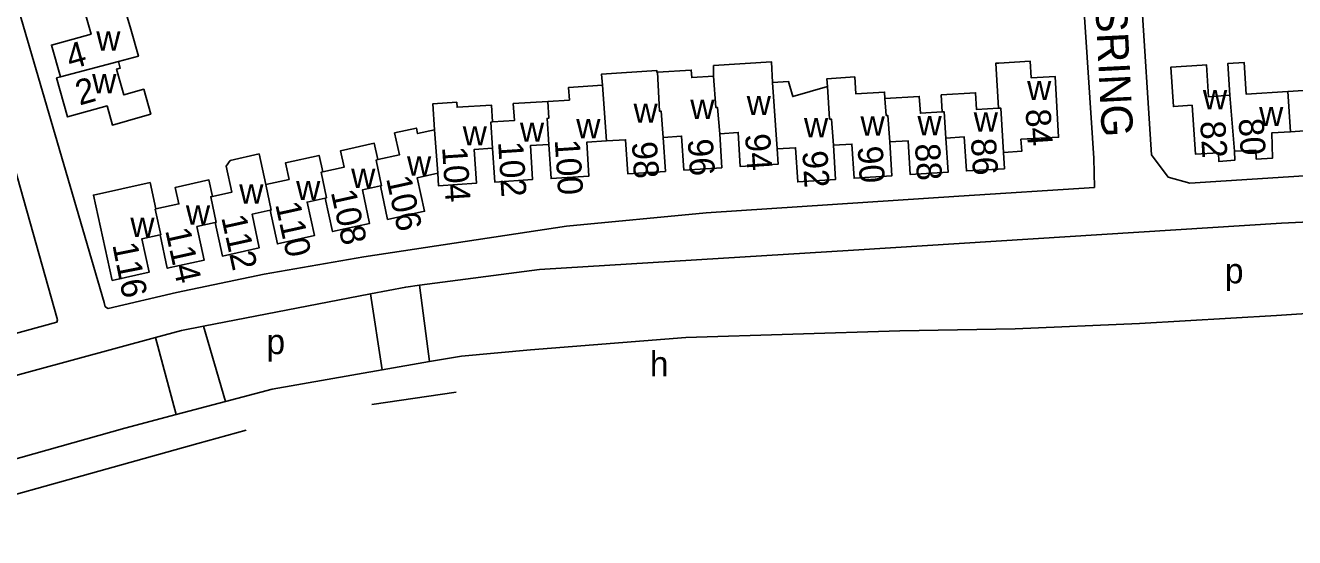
# Model space of a CAD drawing. Extents: x 159441 to 162086, y 388175 to 389787.
# Drawn here: x 160090.5 to 160293, y 388282.9 to 388364.6 of the extents above; entities that cross this region are included whole.
import ezdxf

# ---------------------------------------------------------------- set-up
doc = ezdxf.new("R2010")
doc.units = 0
for name, color, linetype in [('BLT_Basislijn', 7, 'Continuous'), ('BLT_Bebouwing', 7, 'Continuous'), ('BLT_Centroide', 7, 'Continuous'), ('BLT_Huisnummer', 7, 'Continuous'), ('BLT_Huisnummer_ tussenligend', 7, 'Continuous'), ('BLT_Onderverdeling_panden', 7, 'Continuous'), ('BLT_Straatnaam', 7, 'Continuous')]:
    doc.layers.add(name, color=color, linetype=linetype)

msp = doc.modelspace()

# ---------------------------------------------------------------- linework, layer by layer
at = {"layer": 'BLT_Basislijn'}
for p, q in [((160256.8, 388406.25), (160260.99, 388343.47)), ((160103.05, 388320.42), (160085.56, 388380.39)), ((160260.99, 388343.47), (160261.09, 388338.77)), ((160261.09, 388338.77), (160239.41, 388337.36)), ((160239.41, 388337.36), (160199.12, 388334.74)), ((160199.12, 388334.74), (160176.82, 388332.59)), ((160176.82, 388332.59), (160144.51, 388327.71)), ((160144.51, 388327.71), (160128.61, 388324.95)), ((160153.39, 388323.18), (160172.55, 388325.68)), ((160128.61, 388324.95), (160114.6, 388322.05)), ((160114.6, 388322.05), (160103.74, 388319.45)), ((160118.91, 388316.67), (160145.56, 388321.8)), ((160145.56, 388321.8), (160147.41, 388309.68)), ((160153.39, 388323.18), (160155, 388311)), ((160103.26, 388319.74), (160103.05, 388320.42)), ((160103.74, 388319.45), (160103.26, 388319.74)), ((160118.91, 388316.67), (160122.45, 388304.66)), ((160111.29, 388314.87), (160114.54, 388302.55)), ((160160.07, 388311.88), (160155, 388311)), ((160155, 388311), (160147.41, 388309.68)), ((160145.79, 388304.16), (160159.25, 388306.13)), ((160122.45, 388304.66), (160114.54, 388302.55))]:
    msp.add_line(p, q, dxfattribs=at)
for points in [[(160036.37, 388301.08), (160095.52, 388317.29), (160095.65, 388317.66), (160071.61, 388402.93)], [(160268.53, 388369.64), (160270.18, 388343.99), (160272.84, 388340.43), (160276.28, 388339.44), (160347.54, 388344.02)], [(160172.55, 388325.68), (160222.62, 388328.8), (160290.93, 388333.07), (160353.01, 388336.03), (160393.02, 388339)], [(160145.56, 388321.8), (160151.2, 388322.89), (160153.39, 388323.18)], [(160323.1, 388320.51), (160290.1, 388318.37), (160268.27, 388317.06), (160248.4, 388316.24), (160230.01, 388315.91)], [(160111.29, 388314.87), (160115.41, 388315.99), (160118.91, 388316.67)], [(160230.01, 388315.91), (160195.86, 388314.84), (160171.07, 388312.87), (160160.07, 388311.88)], [(160038.47, 388294.65), (160071.9, 388304.16), (160111.29, 388314.87)], [(160147.41, 388309.68), (160129.86, 388306.62), (160122.45, 388304.66)], [(160114.54, 388302.55), (160106.38, 388300.38), (160067.3, 388289.38), (160054.99, 388285.76), (160050.23, 388284.61), (160046.62, 388284.28)], [(160064.32, 388282.94), (160118.04, 388297.92), (160125.75, 388300.05)]]:
    msp.add_lwpolyline(points, dxfattribs=at)
at = {"layer": 'BLT_Bebouwing'}
for points in [[(160100.16, 388366.22), (160100.98, 388363.2), (160094.65, 388361.47), (160096.1, 388356.43)], [(160105.34, 388358.85), (160108.55, 388359.72), (160107.32, 388364), (160106.45, 388367.07), (160106.22, 388367.88)], [(160096.1, 388356.43), (160095.49, 388356.26), (160097.24, 388350.01), (160103.54, 388351.78), (160104.4, 388348.72), (160109.21, 388350.07), (160110.52, 388350.44), (160109.4, 388354.43), (160106.21, 388353.53), (160105.06, 388357.64), (160105.64, 388357.8), (160105.34, 388358.85)], [(160200.32, 388356.53), (160200.3, 388358.2), (160209.56, 388358.8), (160209.71, 388355.51)], [(160245.79, 388351.41), (160245.32, 388358.57), (160245.81, 388358.61), (160250.8, 388358.93), (160250.98, 388356.23), (160254.78, 388356.48), (160255.35, 388346.78), (160249.35, 388346.46), (160249.47, 388344.55), (160246.54, 388344.37)], [(160282.69, 388353.47), (160279.28, 388353.24), (160278.95, 388358.33), (160278.27, 388358.29), (160273.28, 388357.96), (160273.67, 388351.68), (160276.66, 388351.87), (160277.21, 388344.07), (160280.84, 388344.3), (160280.93, 388342.91), (160283.47, 388343.12), (160283.4, 388344.54)], [(160291.92, 388354.06), (160285.29, 388353.63), (160284.96, 388358.72), (160282.37, 388358.55), (160282.69, 388353.47)], [(160301.15, 388354.66), (160300.82, 388359.74), (160298.23, 388359.58), (160298.55, 388354.49), (160291.92, 388354.06)], [(160191.37, 388357.14), (160191.26, 388357.13), (160191.24, 388357.43), (160182.45, 388356.86), (160182.56, 388355.07)], [(160191.37, 388357.14), (160196.74, 388357.49), (160196.82, 388356.3), (160200.32, 388356.53)], [(160218.48, 388354.89), (160218.4, 388356.1), (160222.84, 388356.39), (160223.01, 388353.68), (160227.58, 388353.97), (160227.64, 388352.94)], [(160182.56, 388355.07), (160177.18, 388354.72), (160177.31, 388352.72), (160173.84, 388352.5)], [(160218.48, 388354.89), (160212.93, 388353.27), (160212.28, 388355.67), (160209.71, 388355.51)], [(160236.8, 388350.83), (160236.62, 388353.52), (160242.11, 388353.87), (160242.28, 388351.18), (160245.79, 388351.41)], [(160165.03, 388349.23), (160164.86, 388351.92), (160159.37, 388351.57), (160159.32, 388352.37), (160155.54, 388352.12), (160155.8, 388347.97)], [(160173.84, 388352.5), (160168.35, 388352.14), (160168.52, 388349.45), (160165.03, 388349.23)], [(160227.64, 388352.94), (160233.12, 388353.29), (160233.3, 388350.61), (160236.8, 388350.83)], [(160155.8, 388347.97), (160153.09, 388347.37), (160152.9, 388348.24), (160149.4, 388347.46), (160150.17, 388343.96), (160146.76, 388343.21)], [(160292.33, 388347.67), (160289.35, 388347.48), (160289.49, 388343.47), (160286.9, 388343.3), (160286.83, 388344.71), (160283.4, 388344.54)], [(160301.57, 388345.61), (160298.19, 388345.42), (160298.27, 388344.02), (160295.67, 388343.85), (160295.31, 388347.85), (160292.33, 388347.67)], [(160146.76, 388343.21), (160146.17, 388345.83), (160140.8, 388344.64), (160141.39, 388342.01), (160137.96, 388341.25)], [(160165.04, 388345.02), (160165.38, 388339.63), (160171.41, 388340.02), (160171.08, 388345.45), (160174.04, 388345.63)], [(160174.04, 388345.63), (160174.37, 388340.2), (160180.42, 388340.58), (160180.09, 388346.02), (160183.23, 388346.2)], [(160183.23, 388346.2), (160186.27, 388346.39), (160186.6, 388340.96), (160192.62, 388341.34), (160192.25, 388346.76)], [(160192.25, 388346.76), (160195.2, 388346.96), (160195.57, 388341.54), (160201.62, 388341.91), (160201.28, 388347.35)], [(160201.28, 388347.35), (160204.23, 388347.54), (160204.57, 388342.1), (160210.6, 388342.48), (160210.44, 388344.93)], [(160219.44, 388345.51), (160222.39, 388345.7), (160222.72, 388340.24), (160228.75, 388340.63), (160228.41, 388346.05)], [(160228.41, 388346.05), (160231.34, 388346.23), (160231.68, 388340.82), (160237.71, 388341.21), (160237.36, 388346.65)], [(160246.54, 388344.37), (160246.71, 388341.75), (160240.65, 388341.41), (160240.3, 388346.84), (160237.36, 388346.65)], [(160128.89, 388339.23), (160127.8, 388344.12), (160123.18, 388343.09), (160122.54, 388342.16), (160123.46, 388338.03), (160120.36, 388337.34)], [(160137.96, 388341.25), (160137.37, 388343.89), (160132, 388342.69), (160132.59, 388340.06), (160128.89, 388339.23)], [(160156.29, 388341.03), (160156.41, 388339.05), (160162.46, 388339.45), (160162.12, 388344.84), (160165.04, 388345.02)], [(160210.44, 388344.93), (160213.39, 388345.11), (160213.74, 388339.67), (160219.77, 388340.06), (160219.44, 388345.51)], [(160111.99, 388331.21), (160109.1, 388330.59), (160110.25, 388325.26), (160104.37, 388323.96), (160101.36, 388337.55), (160110.41, 388339.55), (160111.34, 388335.34)], [(160120.36, 388337.34), (160119.78, 388339.98), (160114.41, 388338.78), (160114.99, 388336.15), (160111.34, 388335.34)], [(160147.15, 388339.01), (160148.3, 388333.67), (160154.21, 388334.98), (160153.03, 388340.31), (160156.29, 388341.03)], [(160138.34, 388337.07), (160139.51, 388331.73), (160145.42, 388333.05), (160144.27, 388338.38), (160147.15, 388339.01)], [(160129.57, 388335.13), (160130.73, 388329.78), (160136.63, 388331.1), (160135.46, 388336.43), (160138.34, 388337.07)], [(160120.76, 388333.17), (160121.93, 388327.84), (160127.83, 388329.16), (160126.67, 388334.51), (160129.57, 388335.13)], [(160111.99, 388331.21), (160113.14, 388325.88), (160119.05, 388327.2), (160117.88, 388332.53), (160120.76, 388333.17)]]:
    msp.add_lwpolyline(points, dxfattribs=at)
at = {"layer": 'BLT_Onderverdeling_panden'}
for p, q in [((160096.1, 388356.43), (160105.34, 388358.85)), ((160183.23, 388346.2), (160182.56, 388355.07)), ((160210.44, 388344.93), (160209.71, 388355.51)), ((160291.92, 388354.06), (160292.33, 388347.67)), ((160282.69, 388353.47), (160283.4, 388344.54)), ((160155.8, 388347.97), (160156.29, 388341.03))]:
    msp.add_line(p, q, dxfattribs=at)
for points in [[(160192.25, 388346.76), (160191.94, 388350.96), (160191.66, 388350.94), (160191.37, 388357.14)], [(160201.28, 388347.35), (160200.93, 388351.54), (160200.65, 388351.53), (160200.32, 388356.53)], [(160219.44, 388345.51), (160219.1, 388349.69), (160218.82, 388349.68), (160218.48, 388354.89)], [(160174.04, 388345.63), (160173.73, 388349.78), (160174.01, 388349.8), (160173.84, 388352.5)], [(160228.41, 388346.05), (160228.1, 388350.27), (160227.82, 388350.25), (160227.64, 388352.94)], [(160237.36, 388346.65), (160237.08, 388350.85), (160236.8, 388350.83)], [(160246.54, 388344.37), (160246.12, 388351.43), (160245.79, 388351.41)], [(160165.04, 388345.02), (160164.77, 388349.21), (160165.03, 388349.23)], [(160146.76, 388343.21), (160146.48, 388343.14), (160147.3, 388339.04), (160147.15, 388339.01)], [(160137.96, 388341.25), (160137.68, 388341.19), (160138.53, 388337.11), (160138.34, 388337.07)], [(160128.89, 388339.23), (160129.73, 388335.17), (160129.57, 388335.13)], [(160120.36, 388337.34), (160120.09, 388337.28), (160120.93, 388333.21), (160120.76, 388333.17)], [(160111.34, 388335.34), (160111.22, 388335.31), (160112.11, 388331.24), (160111.99, 388331.21)]]:
    msp.add_lwpolyline(points, dxfattribs=at)

# ---------------------------------------------------------------- texts
at = {"layer": 'BLT_Centroide'}
for s, p in [('w', (160101.81, 388360.61)), ('w', (160101.16, 388353.78)), ('w', (160250.33, 388352.7)), ('w', (160278.38, 388351.22)), ('w', (160187.53, 388349.09)), ('w', (160196.59, 388349.69)), ('w', (160205.59, 388350.31)), ('w', (160178.39, 388346.62)), ('w', (160214.73, 388346.77)), ('w', (160223.75, 388347.02)), ('w', (160232.84, 388347.08)), ('w', (160241.81, 388347.66)), ('w', (160287.34, 388348.55)), ('w', (160160.28, 388345.47)), ('w', (160169.41, 388346.05)), ('w', (160151.39, 388340.67)), ('w', (160142.48, 388338.7)), ('w', (160133.7, 388336.75)), ('w', (160124.62, 388336.2)), ('w', (160116.11, 388332.84)), ('w', (160107.25, 388330.89)), ('p', (160281.88, 388323.49)), ('p', (160128.97, 388312.19)), ('h', (160190.14, 388308.64))]:
    msp.add_text(s, height=4, dxfattribs=at).set_placement(p)
at = {"layer": 'BLT_Huisnummer'}
for s, rotation, p in [('2', 15.705, (160099.15, 388351.83)), ('84', 273.6914, (160250.07, 388351.21)), ('82', 273.7547, (160277.93, 388349.28)), ('100', 273.6914, (160174.96, 388346.35)), ('96', 273.6914, (160196.18, 388346.43)), ('104', 273.6914, (160156.99, 388345.21)), ('92', 273.6914, (160214.46, 388344.54)), ('88', 273.6914, (160232.42, 388345.69)), ('108', 282.423, (160139.22, 388338.04)), ('112', 282.423, (160121.74, 388334.01)), ('116', 281.2163, (160104.37, 388329.65))]:
    msp.add_text(s, height=4, rotation=rotation, dxfattribs=at).set_placement(p)
at = {"layer": 'BLT_Huisnummer_ tussenligend'}
for s, rotation, p in [('4', 15.705, (160097.68, 388357.56)), ('80', 273.7547, (160284.05, 388349.71)), ('102', 273.6914, (160165.92, 388346.03)), ('98', 273.6914, (160187.26, 388346)), ('94', 273.6914, (160205.32, 388347.26)), ('86', 273.6914, (160241.35, 388346.53)), ('90', 273.6914, (160223.28, 388345.28)), ('106', 282.423, (160148.04, 388340.23)), ('110', 282.423, (160130.35, 388336.1)), ('114', 282.423, (160112.8, 388331.94))]:
    msp.add_text(s, height=4, rotation=rotation, dxfattribs=at).set_placement(p)
at = {"layer": 'BLT_Straatnaam'}
msp.add_text('TOPAASRING', height=5, rotation=272.8648, dxfattribs=at).set_placement((160260.09, 388390.47))

doc.saveas('drawing.dxf')
